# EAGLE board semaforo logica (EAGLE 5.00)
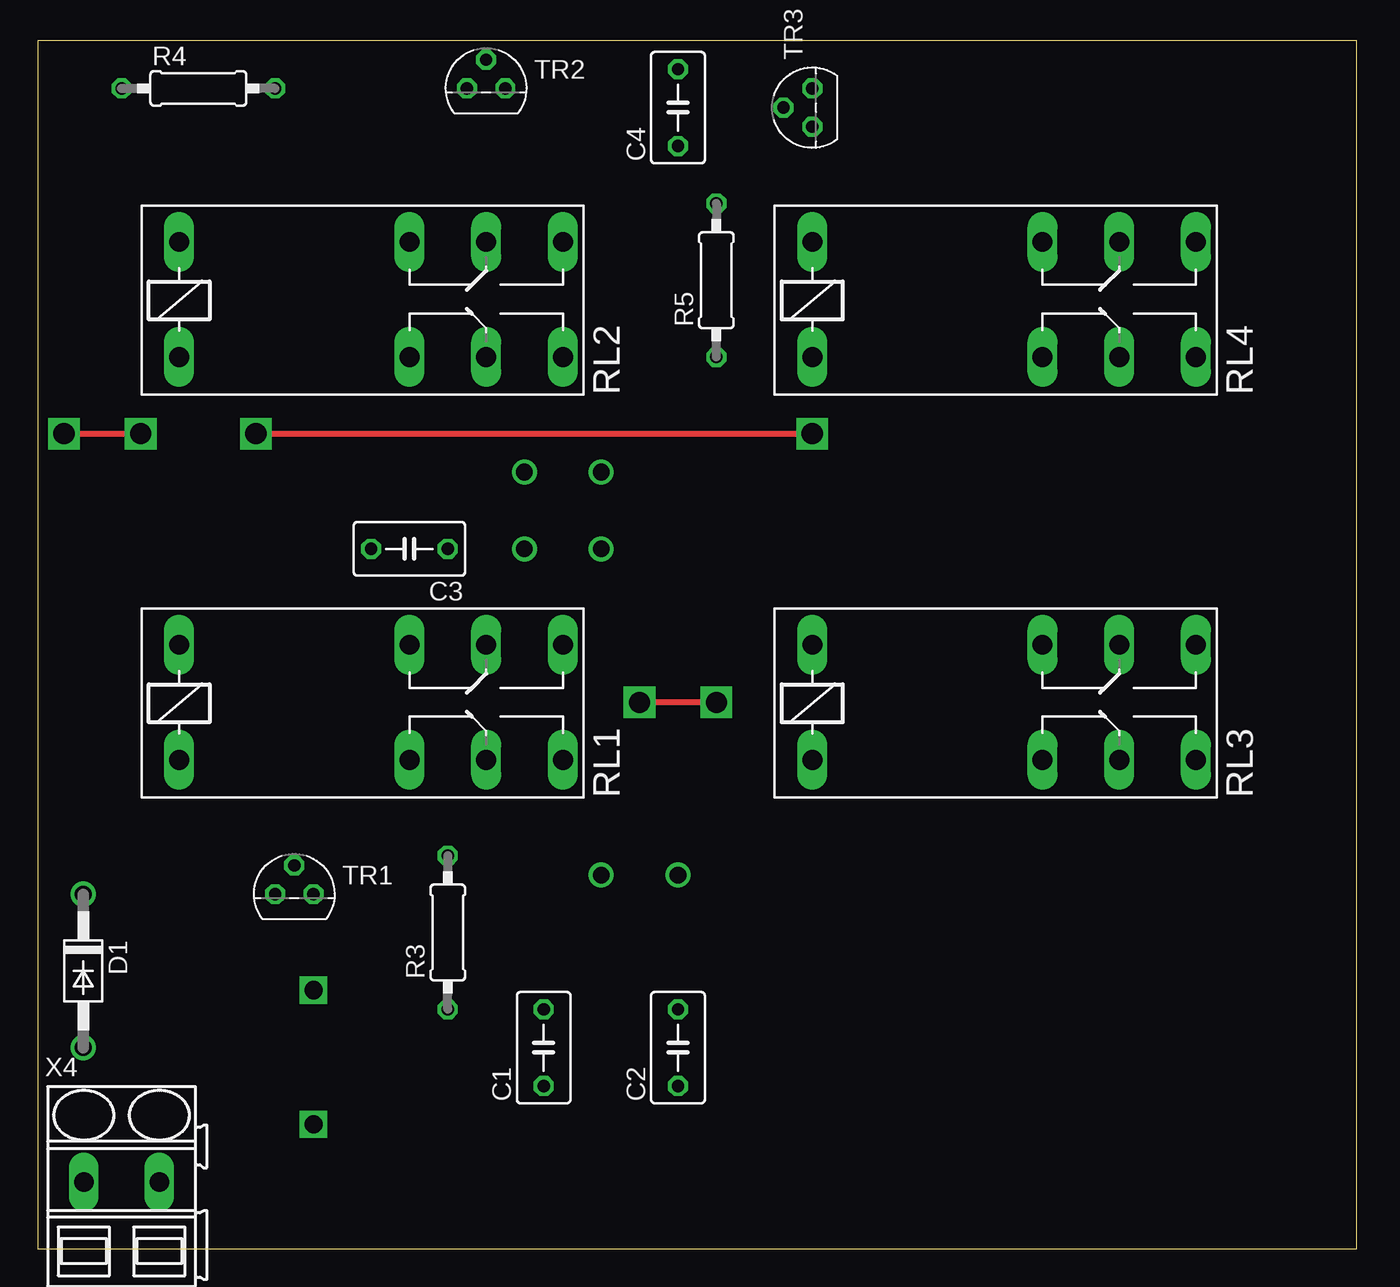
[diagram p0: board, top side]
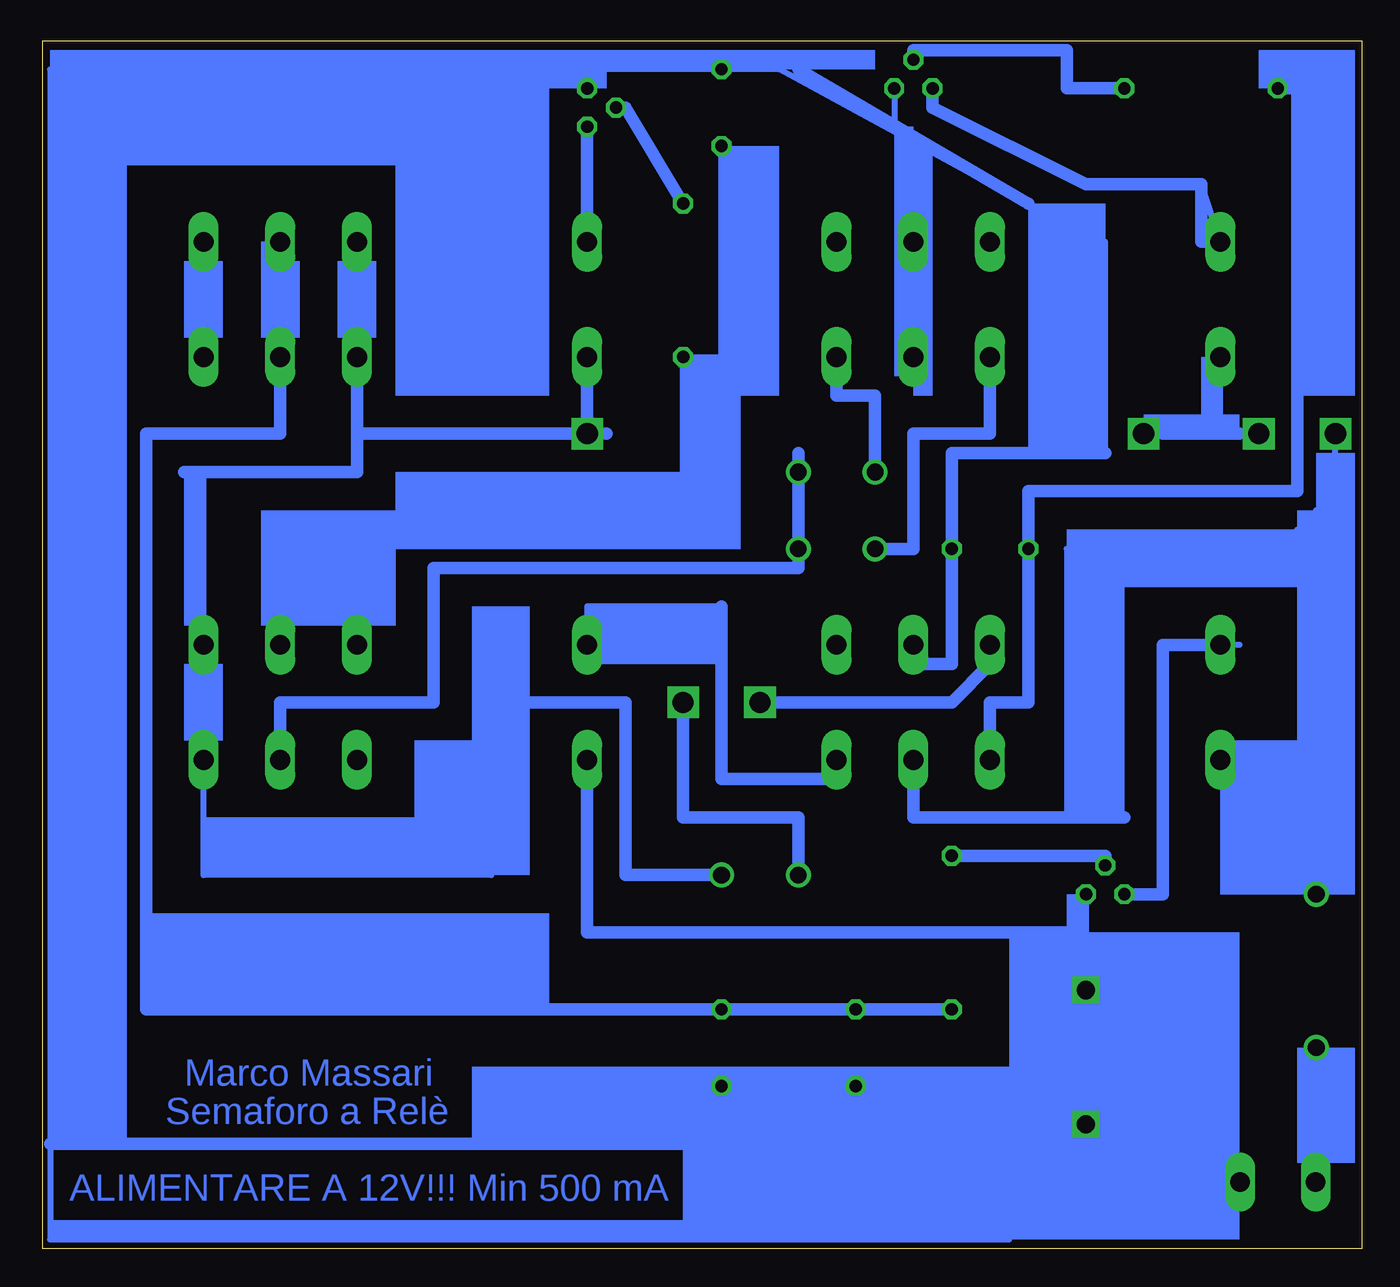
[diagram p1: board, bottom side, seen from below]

Size 87.3 x 80 mm. Coordinates in mm from the lower left corner, seen from the top.
Outline: 0,0 87.3,0 87.3,80 0,80 0,0
Copper layers (1*16): Top 0.035mm / dielectric 1.5mm / Bottom 0.035mm
Design rules "default": minimum track width 10mil, minimum drill 24mil, track to track 8mil, track to pad 8mil, pad to pad 8mil, via to via 8mil, smd to smd 8mil, copper to edge 40mil, drill to drill 8mil, minimum pad ring 10mil, minimum via ring 8mil, stop-mask expansion 4mil, vias tented up to drill 0mil, thermal gap 10mil

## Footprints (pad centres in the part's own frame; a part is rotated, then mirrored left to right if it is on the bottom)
C050-035X075 = drill 0.813 octagon: 1 -2.54,0; 2 2.54,0
DO41-10 = drill 1.118 round: A 5.08,0; C -5.08,0
0207/10 = drill 0.813 octagon: 1 -5.08,0; 2 5.08,0
F4052 = drill 1.321 long: 1 -3.81,3.81; 2 -3.81,-3.81; O1 11.43,-3.81; O2 11.43,3.81; P1 16.51,-3.81; P2 16.51,3.81; S1 21.59,-3.81; S2 21.59,3.81
TO92 = drill 0.813 octagon: 1 1.27,0; 2 0,1.905; 3 -1.27,0
SMKDSP_1,5/2 = drill 1.3 pad 1.676 long: 1 -2.5,0; 2 2.5,0

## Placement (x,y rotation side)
C1  [C050-035X075]  33.49,13.33 90 top
C2  [C050-035X075]  42.38,13.33 90 top
C3  [C050-035X075]  24.6,46.35 180 top
C4  [C050-035X075]  42.38,75.56 90 top
D1  1N4004  [DO41-10]  3.01,18.41 270 top
R3  [0207/10]  27.14,20.95 90 top
R4  [0207/10]  10.63,76.83 0 top
R5  [0207/10]  44.92,64.13 90 top
RL1  4052  [F4052]  13.17,36.19 0 top
RL2  4052  [F4052]  13.17,62.86 0 top
RL3  4052  [F4052]  55.08,36.19 0 top
RL4  4052  [F4052]  55.08,62.86 0 top
TR1  2N3565  [TO92]  16.98,23.49 0 top
TR2  2N3565  [TO92]  29.68,76.83 0 top
TR3  2N3565  [TO92]  51.27,75.56 90 top
X4  SMKDSP_1,5/2  [SMKDSP_1,5/2]  5.55,4.44 0 top

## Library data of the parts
C1-C4 R3-R5 = rcl
D1 = diode
RL1-RL4 = relay
TR1-TR3 = transistor-npn
X4 = con-phoenix-smkdsp

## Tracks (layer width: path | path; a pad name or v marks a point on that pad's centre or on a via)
N$1
  Bottom 0.406: 3.01,4.44 3.01,13.33
N$3
  Bottom 0.406: 8.09,40 9.36,40
  Bottom 0.813: 9.36,40 13.17,40 13.17,23.49 15.71,23.49
N$4  (via drill 1.2)
  Bottom 0.406: 27.14,45.08 27.14,48.89 | 27.14,48.89 27.14,52.7 | 16.98,52.7 16.98,66.67 22.06,69.21 24.6,70.48 38.57,78.1 | 30.95,76.83 30.95,74.29 38.57,78.1 | 38.57,78.1 86.83,78.1 86.83,6.98 86.83,0.63 23.33,0.63 23.33,4.44 | 51.27,33.65 51.27,31.11 | 51.27,20.95 22.06,20.95 22.06,10.79 24.6,10.79 | v18.25,8.25 18.25,6.98 | 18.25,6.98 18.25,3.17 16.98,3.17 | 16.98,3.17 8.09,3.17 8.09,4.44 | 16.98,3.17 23.33,3.17 23.33,4.44 | 23.33,4.44 23.33,10.79 24.6,10.79 | 24.6,10.79 42.38,10.79 | 27.14,38.73 27.14,48.89 | 18.25,23.49 18.25,6.98
  Bottom 0.813: 22.06,69.21 37.3,78.1 | 29.68,38.73 27.14,38.73 27.14,52.7 16.98,52.7 | 19.52,20.95 51.27,20.95 51.27,31.11 | 86.83,6.98 44.92,6.98
N$5
  Bottom 0.813: 16.98,26.03 27.14,26.03
N$6
  Bottom 0.406: 9.36,66.67 10.63,70.48
  Bottom 0.813: 9.36,66.67 10.63,66.67 10.63,70.48 18.25,70.48 28.41,75.56 28.41,76.83
N$7
  Bottom 0.406: 27.14,15.87 79.21,15.87 | 71.59,57.78 71.59,60.32
  Bottom 0.813: 71.59,57.78 71.59,53.97 80.48,53.97 80.48,15.87 | 79.21,15.87 80.48,15.87 | 80.48,15.87 27.14,15.87
N$8
  Bottom 0.406: 42.38,31.11 42.38,36.19 | 42.38,36.19 42.38,40 | 42.38,36.19 42.38,41.27 | 42.38,42.54 51.27,42.54 51.27,38.73
  Bottom 0.813: 34.76,31.11 42.38,31.11 42.38,41.27 42.38,42.54
N$9  (via drill 1.1, 1.4)
  Top 0.406: v14.44,53.97 v51.27,53.97 | v1.74,53.97 v6.82,53.97
  Bottom 0.406: 29.68,28.57 19.52,28.57 19.52,46.35 4.28,46.35 4.28,47.62 3.01,47.62 3.01,46.35 | 3.01,23.49 3.01,31.11 | 3.01,31.11 9.36,31.11 | 3.01,31.11 3.01,46.35 | 3.01,46.35 3.01,48.89 1.74,48.89 v1.74,53.97 | v6.82,53.97 8.09,53.97 9.36,53.97 | 9.36,53.97 9.36,57.78 | v14.44,53.97 13.17,53.97 9.36,53.97 | 56.35,36.19 57.62,36.19 57.62,24.76 76.67,24.76 76.67,36.19 | 76.67,41.27 76.67,38.73 | 76.67,41.27 76.67,51.43 66.51,51.43 | 66.51,57.78 66.51,60.32 | 51.27,57.78 51.27,60.32 | 76.67,31.11 76.67,36.19 | 76.67,36.19 76.67,41.27
  Bottom 0.813: 77.94,51.43 66.51,51.43 66.51,53.97 | 66.51,53.97 66.51,57.78 | 66.51,53.97 v51.27,53.97 | 50,53.97 v51.27,53.97 | v51.27,53.97 51.27,57.78 | 13.17,53.97 8.09,53.97 | 56.35,36.19 48.73,36.19 48.73,24.76 v42.38,24.76 | 29.68,31.11 29.68,28.57 15.71,28.57
N$10
  Bottom 0.406: 4.28,50.16 4.28,53.97 | 4.28,53.97 4.28,56.51 | 4.28,53.97 4.28,59.05 | 4.28,75.56 4.28,76.83
  Bottom 0.813: 24.6,33.65 24.6,36.19 22.06,36.19 22.06,50.16 4.28,50.16 4.28,59.05 4.28,74.29 | 4.28,74.29 4.28,75.56 | 4.28,74.29 4.28,76.83 5.55,76.83
N$11
  Bottom 0.813: 15.71,76.83 19.52,76.83 19.52,79.37 29.68,79.37
N$12  (via drill 1.1)
  Bottom 0.406: 71.59,31.11 71.59,33.65 | 37.3,45.08 v37.3,46.35 v37.3,51.43 37.3,52.7
  Bottom 0.813: v37.3,46.35 37.3,52.7 37.3,45.08 61.43,45.08 61.43,36.19 71.59,36.19 71.59,33.65
N$13  (via drill 1.2)
  other vias: 18.25,17.14
N$14  (via drill 1.1)
  Bottom 0.406: 24.6,57.78 24.6,60.32
  Bottom 0.813: 24.6,57.78 24.6,53.97 29.68,53.97 29.68,46.35 v32.22,46.35
N$15
  Bottom 0.813: 44.92,69.21 48.73,75.56
N$16
  Bottom 0.813: 51.27,65.4 51.27,74.29
N$17  (via drill 1.1)
  Bottom 0.406: 34.76,57.78 34.76,60.32
  Bottom 0.813: v32.22,51.43 32.22,56.51 34.76,56.51 34.76,57.78
N$19
  Bottom 0.406: 44.92,59.05 42.38,59.05 42.38,73.02
N$20
  Bottom 0.406: 44.92,59.05 44.92,47.62 71.59,47.62 71.59,38.73
N$21
  Bottom 0.406: 29.68,57.78 29.68,73.02
N$23  (via drill 1.1, 1.4)
  Top 0.406: v44.92,36.19 v39.84,36.19
  Bottom 0.813: v37.3,24.76 37.3,28.57 44.92,28.57 v44.92,36.19 | v39.84,36.19 27.14,36.19 24.6,38.73
S$1
  Bottom 0.813: 58.89,6.98 83.02,6.98
(copper drawn outside any net)
  shapes: Bottom area x64

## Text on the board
Bottom: Marco Massari | Semaforo a Relè | ALIMENTARE A 12V!!! Min 500 mA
